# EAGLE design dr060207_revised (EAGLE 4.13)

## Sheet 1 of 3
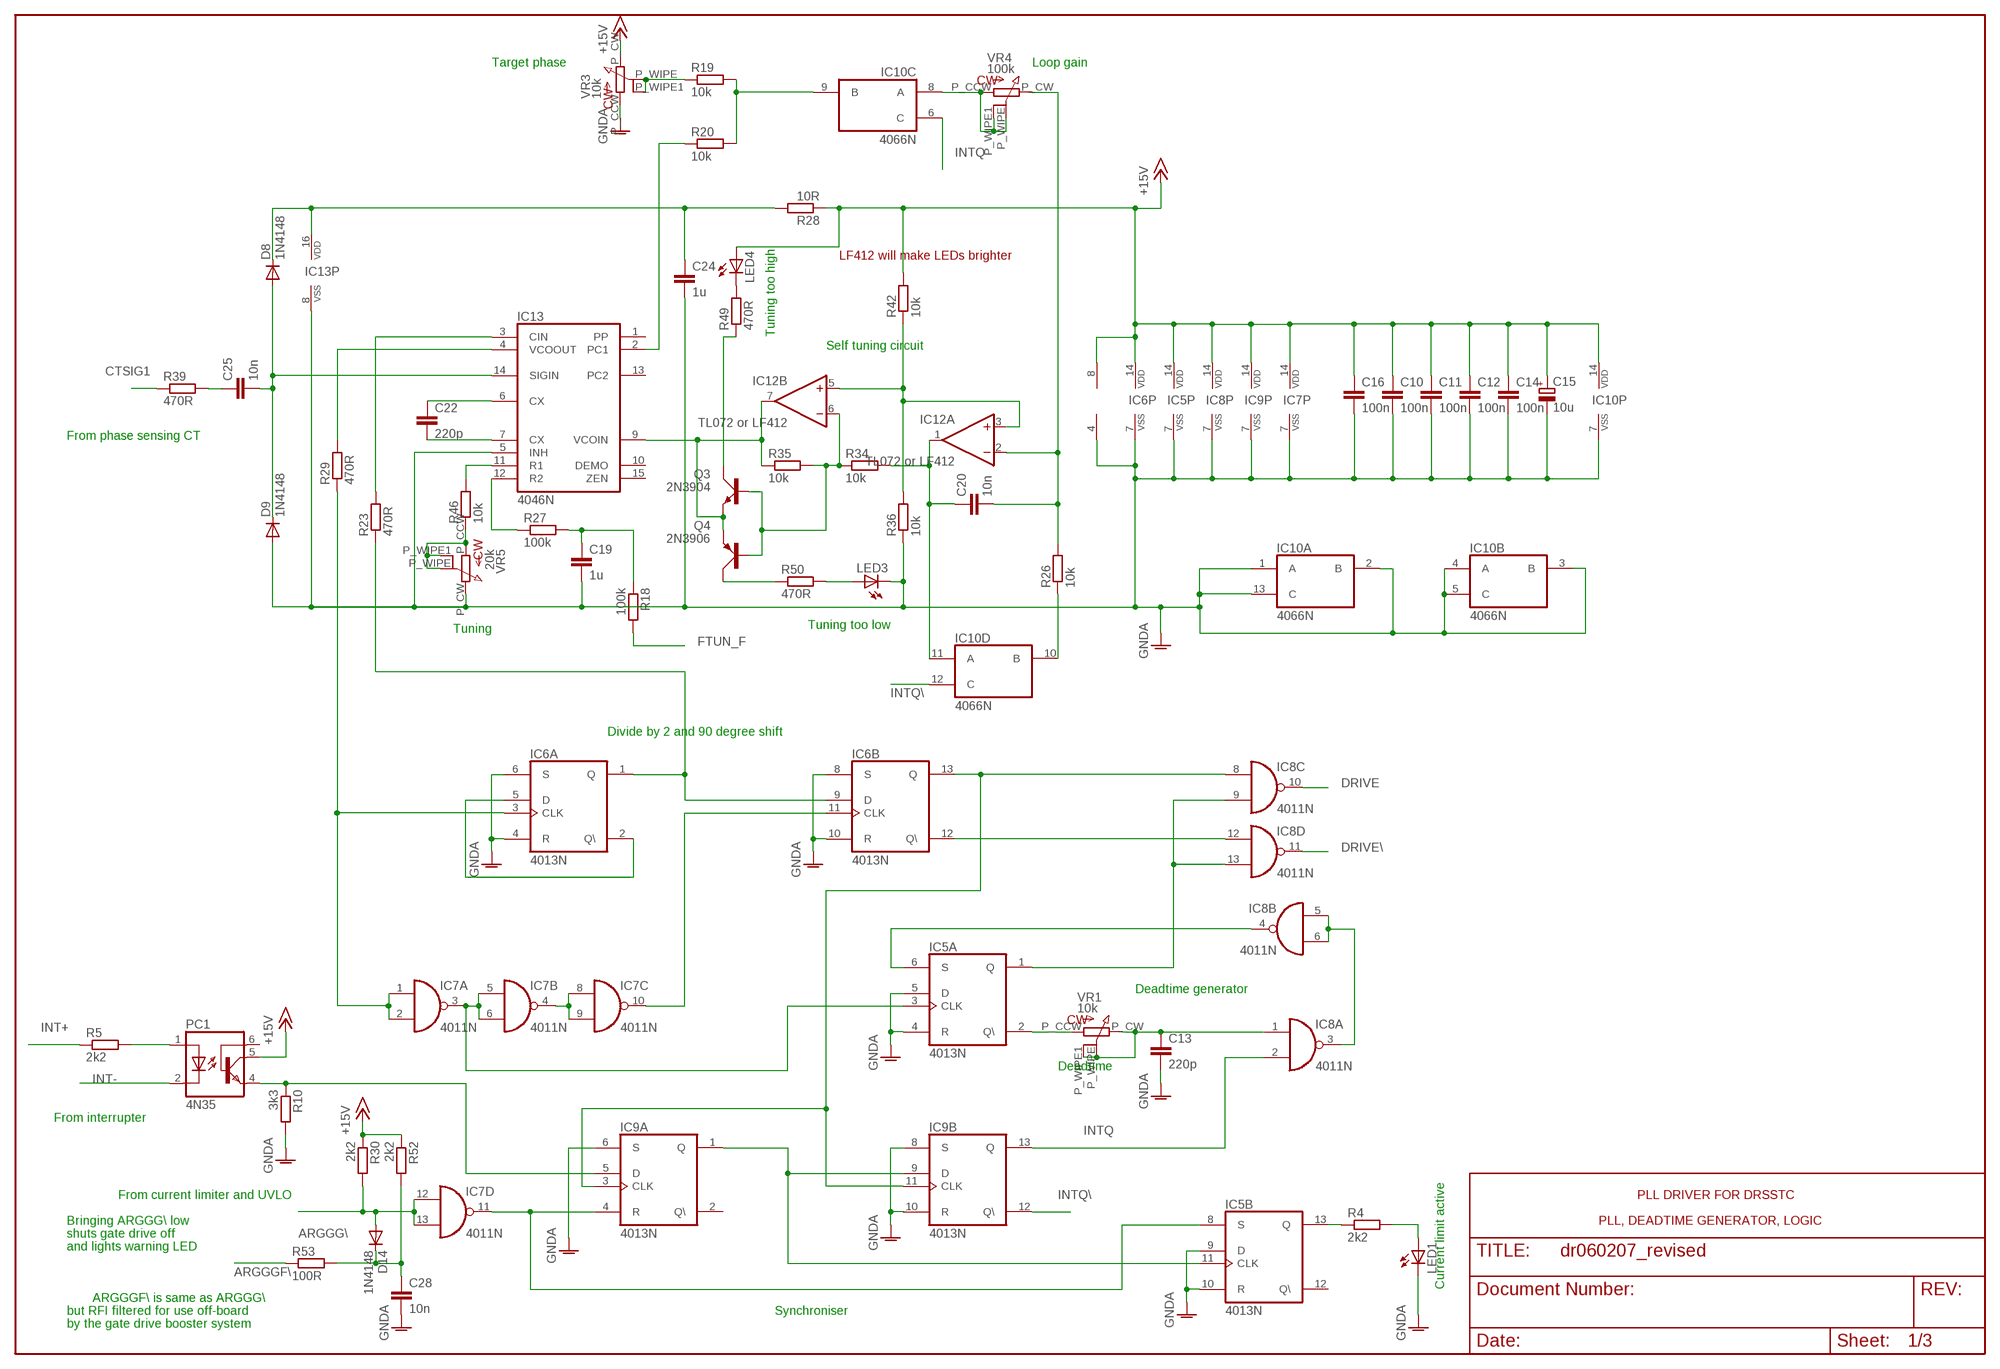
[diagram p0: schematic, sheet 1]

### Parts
C10  100n  C-EU050-025X075  [C050-025X075]
C11  100n  C-EU050-025X075  [C050-025X075]
C12  100n  C-EU050-025X075  [C050-025X075]
C13  220p  C-EU050-025X075  [C050-025X075]
C14  100n  C-EU050-025X075  [C050-025X075]
C15  10u  CPOL-EUTT6D6  [TT5D6]
C16  100n  C-EU050-025X075  [C050-025X075]
C19  1u  C-EU050-025X075  [C050-025X075]
C20  10n  C-EU050-025X075  [C050-025X075]
C22  220p  C-EU050-025X075  [C050-025X075]
C24  1u  C-EU050-055X075  [C050-055X075]
C25  10n  C-EU050-025X075  [C050-025X075]
C28  10n  C-EU050-025X075  [C050-025X075]
D8  1N4148  [DO35-10]
D9  1N4148  [DO35-10]
D14  1N4148  [DO35-10]
IC5  4013N  [DIL14]
IC6  4013N  [DIL14]
IC7  4011N  [DIL14]
IC8  4011N  [DIL14]
IC9  4013N  [DIL14]
IC10  4066N  [DIL14]
IC12  TL072 or LF412  2AMP_P8+4N  [DIL08]
IC13  4046N  [DIL16]
LED1  LED5MM  [LED5MM]
LED3  LED5MM  [LED5MM]
LED4  LED5MM  [LED5MM]
PC1  4N35  [DIL06]
Q3  2N3904  [TO92D]
Q4  2N3906  [TO92D]
R4  2k2  R-EU_0207/10  [0207/10]
R5  2k2  R-EU_0207/10  [0207/10]
R10  3k3  R-EU_0207/10  [0207/10]
R18  100k  R-EU_0207/10  [0207/10]
R19  10k  R-EU_0207/10  [0207/10]
R20  10k  R-EU_0207/10  [0207/10]
R23  470R  R-EU_0207/10  [0207/10]
R26  10k  R-EU_0207/10  [0207/10]
R27  100k  R-EU_0207/10  [0207/10]
R28  10R  R-EU_0207/10  [0207/10]
R29  470R  R-EU_0207/10  [0207/10]
R30  2k2  R-EU_0207/10  [0207/10]
R34  10k  R-EU_0207/10  [0207/10]
R35  10k  R-EU_0207/10  [0207/10]
R36  10k  R-EU_0207/10  [0207/10]
R39  470R  R-EU_0207/10  [0207/10]
R42  10k  R-EU_0207/10  [0207/10]
R46  10k  R-EU_0207/10  [0207/10]
R49  470R  R-EU_0207/10  [0207/10]
R50  470R  R-EU_0207/10  [0207/10]
R52  2k2  R-EU_0207/10  [0207/10]
R53  100R  R-EU_0207/10  [0207/10]
VR1  10k  POT  [SPECTROL149]
VR3  10k  POT  [SPECTROL149]
VR4  100k  POT  [SPECTROL149]
VR5  20k  POT  [SPECTROL149]

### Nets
+15V: C10.1 C11.1 C12.1 C14.1 C15.+ C16.1 IC5.14(P:VDD) IC6.14(P:VDD) IC7.14(P:VDD) IC8.14(P:VDD) IC9.14(P:VDD) IC10.14(P:VDD) IC12.8(P:V+) LED4.A PC1.5(COL) R28.1 R30.1 R42.2 R52.1 VR3.P_CW(CW) ; also sheet 2,3
ARGGG\: D14.A IC7.12(D:I0) IC7.13(D:I1) R30.2 ; also sheet 2
ARGGGF\: R53.1 ; also sheet 3
CTSIG1: R39.1 ; also sheet 3
DRIVE: IC8.10(C:O) ; also sheet 3
DRIVE\: IC8.11(D:O) ; also sheet 3
FTUN_F: R18.2 ; also sheet 3
GNDA: C10.2 C11.2 C12.2 C13.2 C14.2 C15.- C16.2 C19.2 C24.2 C28.2 D9.A IC5.4(A:R) IC5.5(A:D) IC5.7(P:VSS) IC5.9(B:D) IC5.10(B:R) IC6.4(A:R) IC6.6(A:S) IC6.7(P:VSS) IC6.8(B:S) IC6.10(B:R) IC7.7(P:VSS) IC8.7(P:VSS) IC9.6(A:S) IC9.7(P:VSS) IC9.8(B:S) IC9.10(B:R) IC10.1(A:A) IC10.2(A:B) IC10.3(B:B) IC10.4(B:A) IC10.5(B:C) IC10.7(P:VSS) IC10.13(A:C) IC12.4(P:V-) IC13.5(INH) IC13.8(VSS) LED1.K(C) LED3.K(C) R10.2 R36.1 VR3.P_CCW(CCW) VR5.P_CW(CW) ; also sheet 2,3
INT+: R5.1 ; also sheet 3
INT-: PC1.2(C) ; also sheet 3
INTQ: IC8.2(A:I1) IC9.13(B:Q) IC10.6(C:C)
INTQ\: IC9.12(B:Q\) IC10.12(D:C)
N$1: C22.2 IC13.7(CX)
N$2: IC10.10(D:B) R26.1
N$3: IC12.7(B:OUT) IC13.9(VCOIN) Q3.E Q4.E R35.1
N$4: IC12.3(A:+IN) IC12.5(B:+IN) R36.2 R42.1
N$5: C24.1 D8.C IC13.16(VDD) R28.2
N$7: C22.1 IC13.6(CX)
N$8: IC6.2(A:Q\) IC6.5(A:D)
N$9: IC6.1(A:Q) IC6.9(B:D) R23.1
N$10: IC13.3(CIN) R23.2
N$11: IC13.11(R1) R46.2
N$12: IC9.5(A:D) PC1.4(EMI) R10.1
N$13: IC5.3(A:CLK) IC7.3(A:O) IC7.5(B:I0) IC7.6(B:I1)
N$14: R46.1 VR5.P_CCW(CCW) VR5.P_WIPE1(WIPE1) VR5.P_WIPE(WIPE)
N$16: IC7.4(B:O) IC7.8(C:I0) IC7.9(C:I1)
N$17: C20.1 IC10.11(D:A) IC12.1(A:OUT) R34.2
N$18: IC6.11(B:CLK) IC7.10(C:O)
N$19: C20.2 IC12.2(A:-IN) R26.2 VR4.P_CW(CW)
N$20: C25.2 D8.A D9.C IC13.14(SIGIN)
N$22: IC13.4(VCOOUT) R29.2
N$23: IC6.3(A:CLK) IC7.1(A:I0) IC7.2(A:I1) R29.1
N$26: PC1.1(A) R5.2
N$29: C25.1 R39.2
N$31: C13.1 IC8.1(A:I0) VR1.P_CW(CW) VR1.P_WIPE1(WIPE1) VR1.P_WIPE(WIPE)
N$32: IC5.1(A:Q) IC8.9(C:I1) IC8.13(D:I1)
N$33: IC6.13(B:Q) IC8.8(C:I0) IC9.3(A:CLK) IC9.11(B:CLK)
N$34: IC6.12(B:Q\) IC8.12(D:I0)
N$35: IC5.6(A:S) IC8.4(B:O)
N$36: IC8.3(A:O) IC8.5(B:I0) IC8.6(B:I1)
N$39: IC5.11(B:CLK) IC9.1(A:Q) IC9.9(B:D)
N$40: IC5.8(B:S) IC7.11(D:O) IC9.4(A:R)
N$42: IC12.6(B:-IN) Q3.B Q4.B R34.1 R35.2
N$43: LED1.A R4.2
N$44: IC5.13(B:Q) R4.1
N$47: IC10.9(C:B) R19.2 R20.2
N$48: IC13.2(PC1) R20.1
N$49: R19.1 VR3.P_WIPE1(WIPE1) VR3.P_WIPE(WIPE)
N$50: IC10.8(C:A) VR4.P_CCW(CCW) VR4.P_WIPE1(WIPE1) VR4.P_WIPE(WIPE)
N$51: Q4.C R50.1
N$52: LED3.A R50.2
N$53: LED4.K(C) R49.2
N$54: Q3.C R49.1
N$70: IC5.2(A:Q\) VR1.P_CCW(CCW)
N$71: IC13.12(R2) R27.1
N$72: C19.1 R18.1 R27.2
N$666: C28.1 D14.C R52.2 R53.2
Unconnected: IC5.12(B:Q\) IC9.2(A:Q\) IC13.1(PP) IC13.10(DEMO) IC13.13(PC2) IC13.15(ZEN) PC1.6(BAS)

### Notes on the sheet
- Target phase | Loop gain
- LF412 will make LEDs brighter
- Tuning too high
- Self tuning circuit
- From phase sensing CT
- Tuning too low
- Tuning
- Divide by 2 and 90 degree shift
- Deadtime generator
- Deadtime
- From interrupter
- From current limiter and UVLO | PLL DRIVER FOR DRSSTC
- Bringing ARGGG\ low | PLL, DEADTIME GENERATOR, LOGIC
- shuts gate drive off
- and lights warning LED
- Current limit active
- ARGGGF\ is same as ARGGG\
- but RFI filtered for use off-board | Synchroniser
- by the gate drive booster system

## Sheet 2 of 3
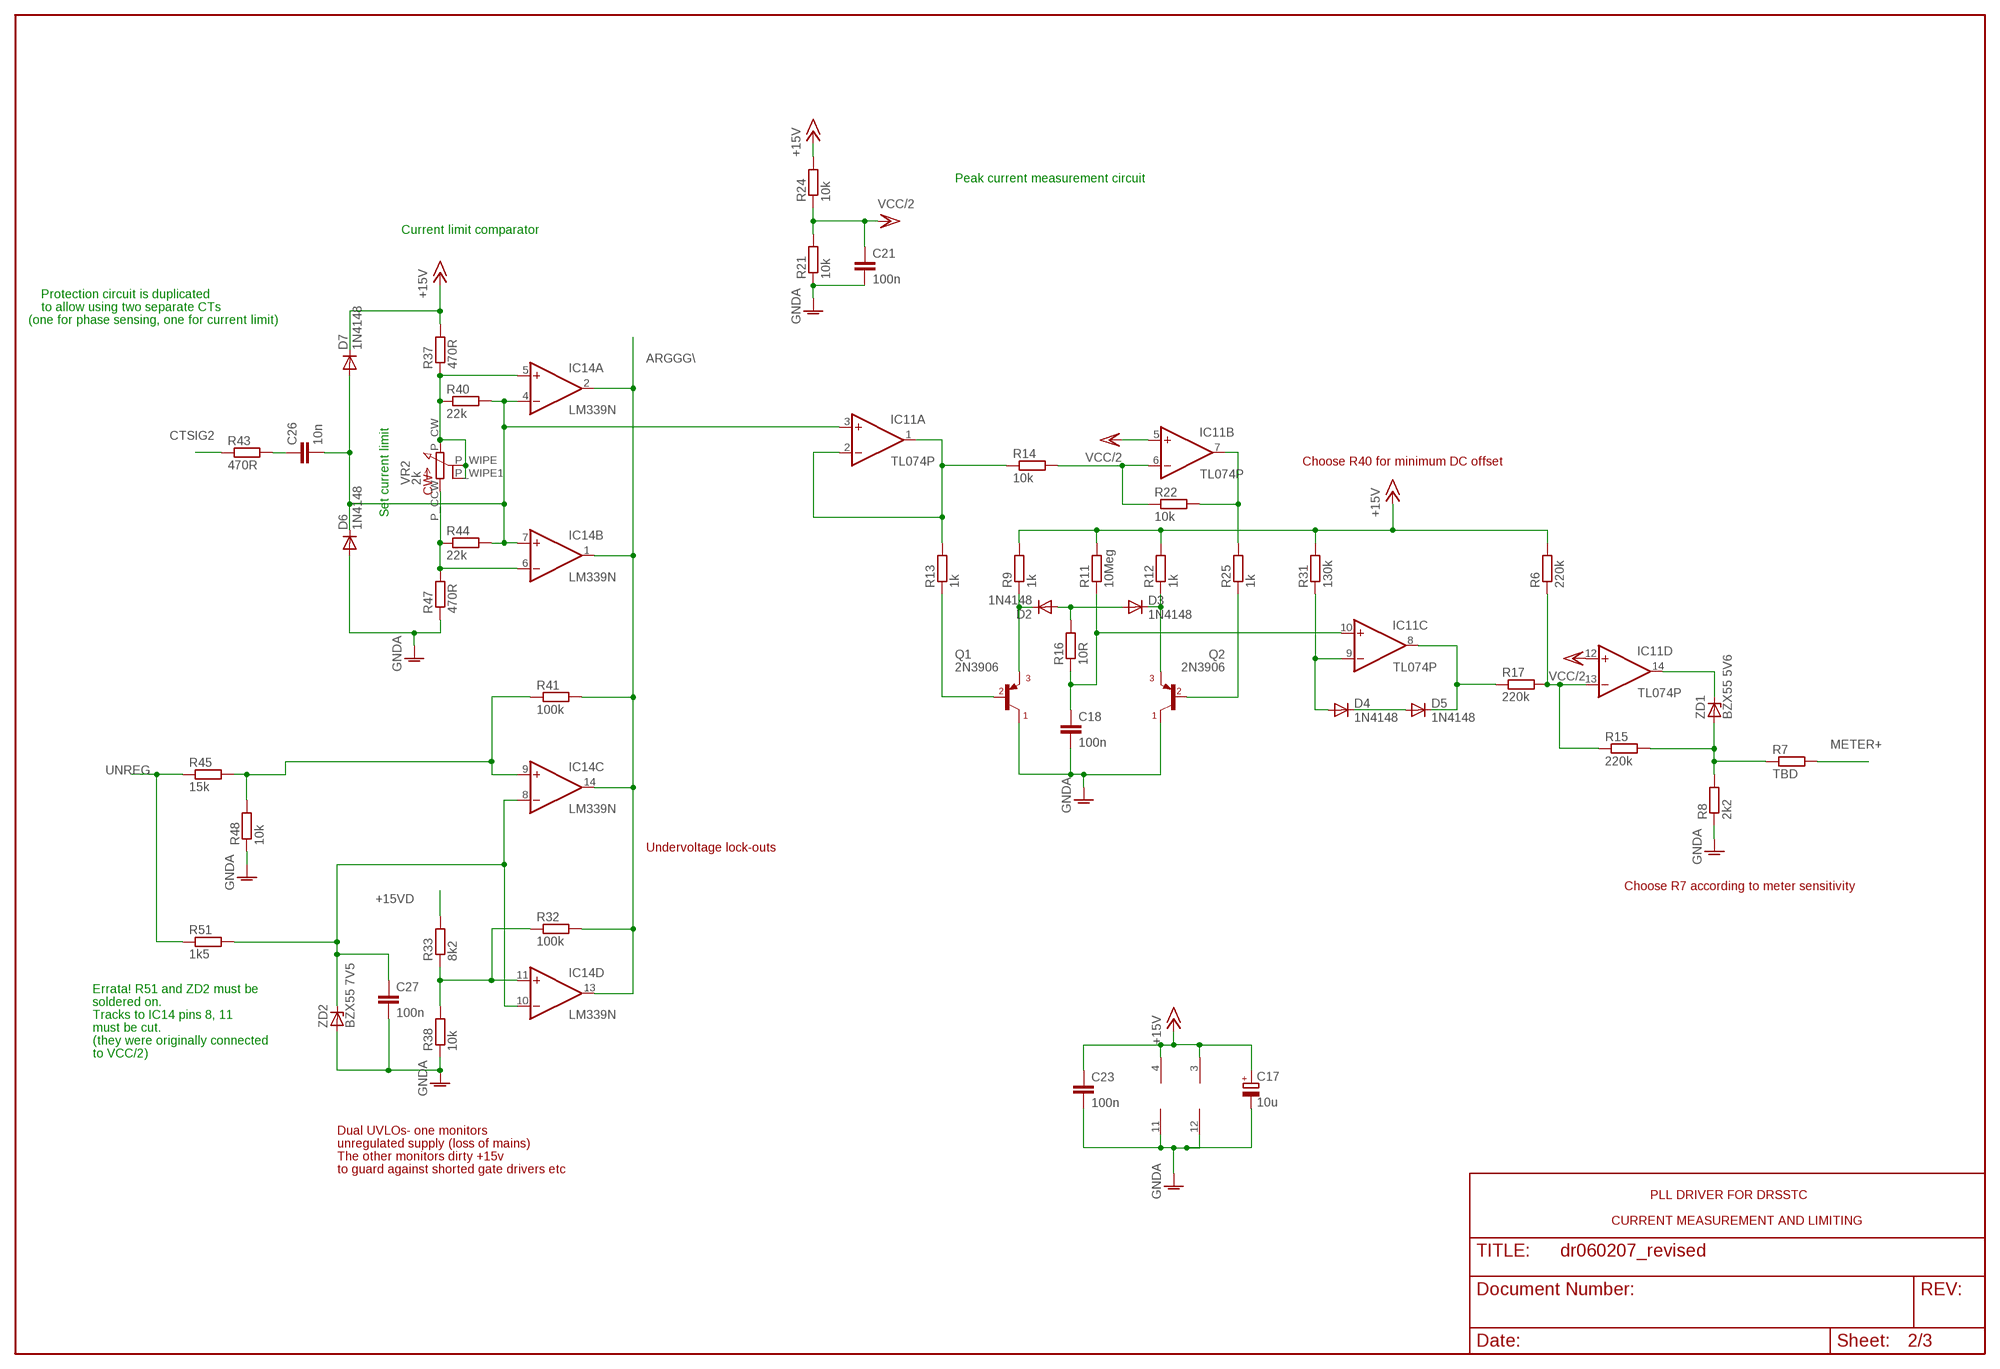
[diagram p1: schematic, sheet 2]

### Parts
C17  10u  CPOL-EUTT6D6  [TT5D6]
C18  100n  C-EU050-025X075  [C050-025X075]
C21  100n  C-EU050-025X075  [C050-025X075]
C23  100n  C-EU050-025X075  [C050-025X075]
C26  10n  C-EU050-025X075  [C050-025X075]
C27  100n  C-EU050-025X075  [C050-025X075]
D2  1N4148  [DO35-10]
D3  1N4148  [DO35-10]
D4  1N4148  [DO35-10]
D5  1N4148  [DO35-10]
D6  1N4148  [DO35-10]
D7  1N4148  [DO35-10]
IC11  TL074P  [DIL14]
IC14  LM339N  [DIL14]
Q1  2N3906  [TO92]
Q2  2N3906  [TO92]
R6  220k  R-EU_0207/10  [0207/10]
R7  TBD  R-EU_0207/10  [0207/10]
R8  2k2  R-EU_0207/10  [0207/10]
R9  1k  R-EU_0207/10  [0207/10]
R11  10Meg  R-EU_0207/10  [0207/10]
R12  1k  R-EU_0207/10  [0207/10]
R13  1k  R-EU_0207/10  [0207/10]
R14  10k  R-EU_0207/10  [0207/10]
R15  220k  R-EU_0207/10  [0207/10]
R16  10R  R-EU_0207/10  [0207/10]
R17  220k  R-EU_0207/10  [0207/10]
R21  10k  R-EU_0207/10  [0207/10]
R22  10k  R-EU_0207/10  [0207/10]
R24  10k  R-EU_0207/10  [0207/10]
R25  1k  R-EU_0207/10  [0207/10]
R31  130k  R-EU_0207/10  [0207/10]
R32  100k  R-EU_0207/10  [0207/10]
R33  8k2  R-EU_0207/10  [0207/10]
R37  470R  R-EU_0207/10  [0207/10]
R38  10k  R-EU_0207/10  [0207/10]
R40  22k  R-EU_0207/10  [0207/10]
R41  100k  R-EU_0207/10  [0207/10]
R43  470R  R-EU_0207/10  [0207/10]
R44  22k  R-EU_0207/10  [0207/10]
R45  15k  R-EU_0207/10  [0207/10]
R47  470R  R-EU_0207/10  [0207/10]
R48  10k  R-EU_0207/10  [0207/10]
R51  1k5  R-EU_0207/10  [0207/10]
VR2  2k  POT  [SPECTROL149]
ZD1  BZX55 5V6  BZX55  [DO35Z10]
ZD2  BZX55 7V5  BZX55  [DO35Z10]

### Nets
+15V: C17.+ C23.1 D7.C IC11.4(P:V+) IC14.3(P:V+) R6.2 R9.2 R11.2 R12.2 R24.2 R31.2 R37.2 ; also sheet 1,3
+15VD: R33.2 ; also sheet 3
ARGGG\: IC14.1(B:OUT) IC14.2(A:OUT) IC14.13(D:OUT) IC14.14(C:OUT) R32.2 R41.2 ; also sheet 1
CTSIG2: R43.1 ; also sheet 3
GNDA: C17.- C18.2 C21.2 C23.2 C27.2 D6.A IC11.11(P:V-) IC14.12(P:GND) Q1.1(C) Q2.1(C) R8.1 R21.1 R38.1 R47.1 R48.1 ZD2.A ; also sheet 1,3
METER+: R7.2 ; also sheet 3
N$24: IC14.9(C:+IN) R41.1 R45.2 R48.2
N$27: IC11.6(B:-IN) R14.2 R22.1
N$28: IC11.1(A:OUT) IC11.2(A:-IN) R13.2 R14.1
N$37: C26.1 R43.2
N$38: IC14.11(D:+IN) R32.1 R33.1 R38.2
N$41: IC11.7(B:OUT) R22.2 R25.2
N$45: C26.2 D6.C D7.A IC11.3(A:+IN) IC14.4(A:-IN) IC14.7(B:+IN) R40.2 R44.2
N$46: Q1.2(B) R13.1
N$55: IC14.6(B:-IN) R44.1 R47.2 VR2.P_CCW(CCW)
N$56: IC14.5(A:+IN) R37.1 R40.1 VR2.P_CW(CW) VR2.P_WIPE1(WIPE1) VR2.P_WIPE(WIPE)
N$57: Q2.2(B) R25.1
N$58: D2.C Q1.3(E) R9.1
N$59: D3.C Q2.3(E) R12.1
N$60: D2.A D3.A R16.2
N$61: C18.1 IC11.10(C:+IN) R11.1 R16.1
N$63: D5.C IC11.8(C:OUT) R17.1
N$64: D4.C D5.A
N$65: D4.A IC11.9(C:-IN) R31.1
N$66: IC11.13(D:-IN) R6.1 R15.1 R17.2
N$67: IC11.14(D:OUT) ZD1.C
N$68: R7.1 R8.2 R15.2 ZD1.A
N$75: C27.1 IC14.8(C:-IN) IC14.10(D:-IN) R51.2 ZD2.C
UNREG: R45.1 R51.1 ; also sheet 3
VCC/2: C21.1 IC11.5(B:+IN) IC11.12(D:+IN) R21.2 R24.1

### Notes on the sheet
- Peak current measurement circuit
- Current limit comparator
- Protection circuit is duplicated
- to allow using two separate CTs
- (one for phase sensing, one for current limit)
- Choose R40 for minimum DC offset
- Set current limit
- Undervoltage lock-outs
- Choose R7 according to meter sensitivity
- Errata! R51 and ZD2 must be
- soldered on.
- Tracks to IC14 pins 8, 11
- must be cut.
- (they were originally connected
- to VCC/2)
- Dual UVLOs- one monitors
- unregulated supply (loss of mains)
- The other monitors dirty +15v
- to guard against shorted gate drivers etc
- PLL DRIVER FOR DRSSTC
- CURRENT MEASUREMENT AND LIMITING

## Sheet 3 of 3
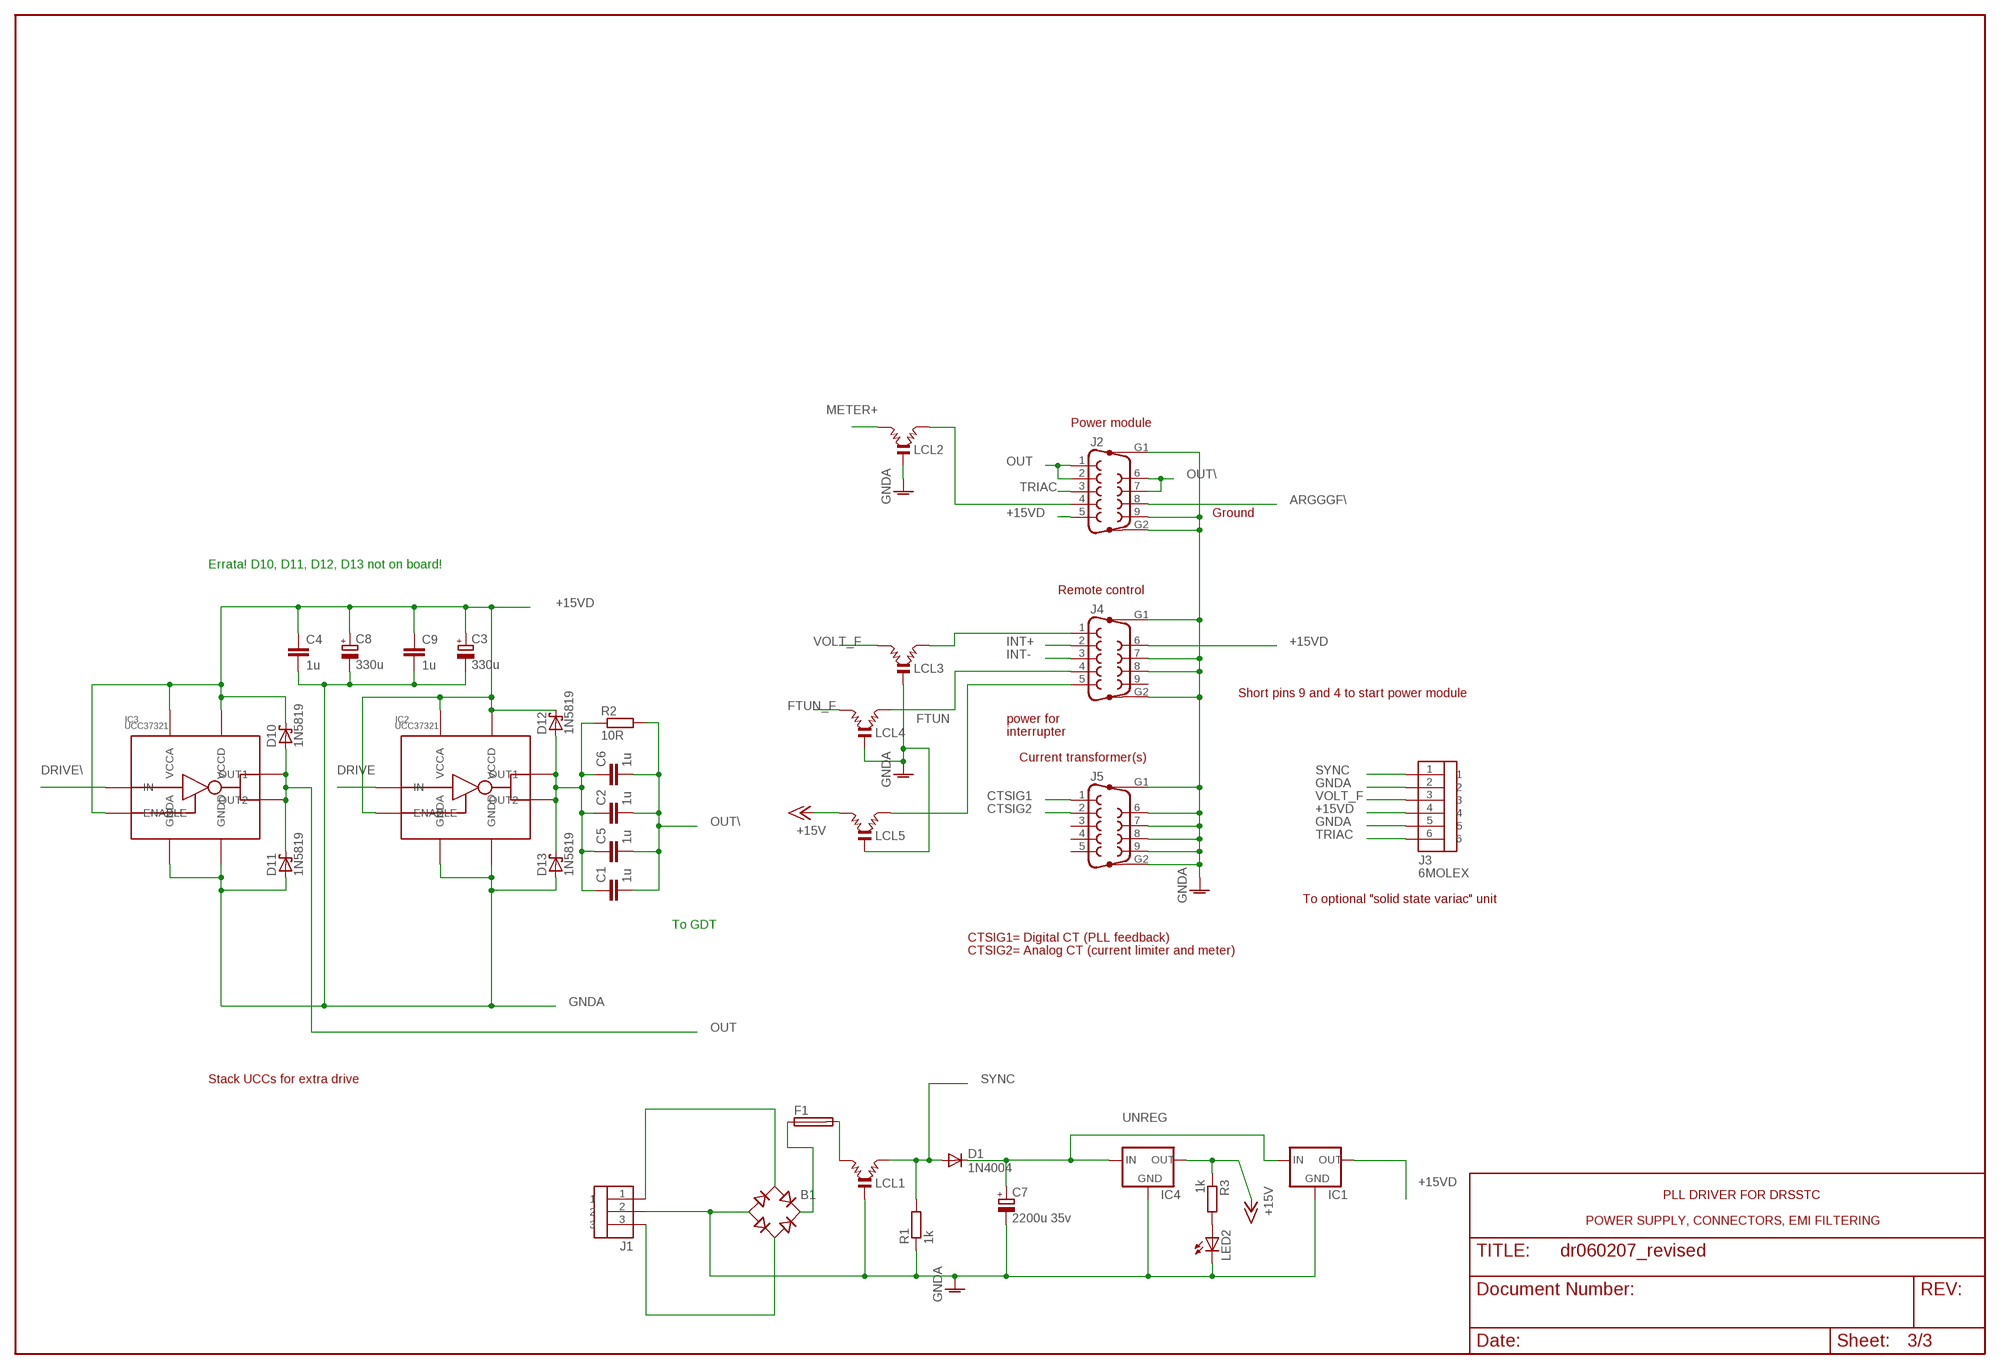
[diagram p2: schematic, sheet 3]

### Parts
B1  RB1A  [RB1A]
C1  1u  C-EU050-055X075  [C050-055X075]
C2  1u  C-EU050-055X075  [C050-055X075]
C3  330u  CPOL-EUE3.5-10  [E3,5-10]
C4  1u  C-EU050-025X075  [C050-025X075]
C5  1u  C-EU050-055X075  [C050-055X075]
C6  1u  C-EU050-055X075  [C050-055X075]
C7  2200u 35v  CPOL-EUE7.5-18  [E7,5-18]
C8  330u  CPOL-EUE3.5-10  [E3,5-10]
C9  1u  C-EU050-025X075  [C050-025X075]
D1  1N4004  [DO41-10]
D10  1N5819  SCHOTTKY-DIODECORNFIELD  [CORNFIELD]
D11  1N5819  SCHOTTKY-DIODECORNFIELD  [CORNFIELD]
D12  1N5819  SCHOTTKY-DIODECORNFIELD  [CORNFIELD]
D13  1N5819  SCHOTTKY-DIODECORNFIELD  [CORNFIELD]
F1  SH22,5  [SH22,5]
IC1  78XXS  [78XXS]
IC2  UCC37321  [DIL08]
IC3  UCC37321  [DIL08]
IC4  78XXS  [78XXS]
J1  P3-5  [P3-5]
J2  F09HP  [F09HP]
J3  6MOLEX  [6MOLEX]
J4  F09HP  [F09HP]
J5  F09HP  [F09HP]
LCL1  LCL  [LCL]
LCL2  LCL  [LCL]
LCL3  LCL  [LCL]
LCL4  LCL  [LCL]
LCL5  LCL  [LCL]
LED2  LED5MM  [LED5MM]
R1  1k  R-EU_0207/10  [0207/10]
R2  10R  R-EU_0207/10  [0207/10]
R3  1k  R-EU_0207/10  [0207/10]

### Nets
+15V: IC4.OUT LCL5.1 R3.1 ; also sheet 1,2
+15VD: C3.+ C4.1 C8.+ C9.1 D10.C D12.C IC1.OUT IC2.1(VCCA) IC2.3(ENABLE) IC2.8(VCCD) IC3.1(VCCA) IC3.3(ENABLE) IC3.8(VCCD) J2.5 J3.4 J4.6 ; also sheet 2
ARGGGF\: J2.8 ; also sheet 1
CTSIG1: J5.1 ; also sheet 1
CTSIG2: J5.2 ; also sheet 2
DRIVE: IC2.2(IN) ; also sheet 1
DRIVE\: IC3.2(IN) ; also sheet 1
FTUN: J4.4 LCL4.2
FTUN_F: LCL4.1 ; also sheet 1
GNDA: B1.- C3.- C4.2 C7.- C8.- C9.2 D11.A D13.A IC1.GND IC2.4(GNDA) IC2.5(GNDD) IC3.4(GNDA) IC3.5(GNDD) IC4.GND J1.2 J2.9 J2.G1 J2.G2 J3.2 J3.5 J4.7 J4.8 J4.G1 J4.G2 J5.6 J5.7 J5.8 J5.9 J5.G1 J5.G2 LCL1.0(GND) LCL2.0(GND) LCL3.0(GND) LCL4.0(GND) LCL5.0(GND) LED2.K(C) R1.1 ; also sheet 1,2
INT+: J4.2 ; also sheet 1
INT-: J4.3 ; also sheet 1
METER+: LCL2.1 ; also sheet 2
N$6: J4.1 LCL3.2
N$15: J2.4 LCL2.2
N$21: B1.+ F1.1
N$25: B1.AC1 J1.1
N$30: J4.5 LCL5.2
N$62: B1.AC2 J1.3
N$69: LED2.A R3.2
N$73: C1.1 C2.1 C5.1 C6.1 D12.A D13.C IC2.6(OUT2) IC2.7(OUT1) R2.1
N$74: F1.2 LCL1.1
OUT: D10.A D11.C IC3.6(OUT2) IC3.7(OUT1) J2.1 J2.2
OUT\: C1.2 C2.2 C5.2 C6.2 J2.6 J2.7 R2.2
SYNC: D1.A J3.1 LCL1.2 R1.2
TRIAC: J2.3 J3.6
UNREG: C7.+ D1.C IC1.IN IC4.IN ; also sheet 2
VOLT_F: J3.3 LCL3.1
Unconnected: J4.9 J5.3 J5.4 J5.5

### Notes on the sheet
- Power module
- Ground
- Errata! D10, D11, D12, D13 not on board!
- Remote control
- Short pins 9 and 4 to start power module
- power for
- interrupter
- Current transformer(s)
- To optional "solid state variac" unit
- To GDT
- CTSIG1= Digital CT (PLL feedback)
- CTSIG2= Analog CT (current limiter and meter)
- Stack UCCs for extra drive
- PLL DRIVER FOR DRSSTC
- POWER SUPPLY, CONNECTORS, EMI FILTERING

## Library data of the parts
B1 = rectifier:RB1A: RECTIFIER 1 A
C1 C2 C4-C6 C9-C14 C16 C18 C19 C21-C27 = rcl:C-EU: CAPACITOR, European symbol
C3 C7 C8 C15 C17 = rcl:CPOL-EU: POLARIZED CAPACITOR, European symbol
C20 C28 = rcl_dm:C-EU: CAPACITOR, European symbol
D1 = diode:1N4004: DIODE
D2-D9 D14 = diode:1N4148: DIODE
D10-D13 = diode:SCHOTTKY-DIODE: Schottky Diode
F1 = fuse:SH22,5: FUSE HOLDER
IC1 IC4 = v-reg:78XXS: VOLTAGE REGULATOR
IC2 IC3 = tesla:UCC37321
IC5 IC6 IC9 = 40xx:4013: Dual D FLIP FLOP, set/reset
IC7 IC8 = 40xx:4011: Quad 2-input NAND
IC10 = 40xx:4066: Quad bilateral ANALOG SWITCH
IC11 = linear_optosci:TL074: OP AMP
IC12 = linear:2AMP_P8+4: OP AMP
IC13 = 40xx:4046: Micropower PLL
IC14 = linear_optosci:LM339: Low Power Low Offset Voltage Quad Comparators with open collector; LM139/LM239/LM339/LM2901/LM3302
J1 = CONNDM:P3-5
J2 J4 J5 = con-subd:F09HP: SUB-D
J3 = CONNDM:6MOLEX
LCL1-LCL5 = murata-filter:LCL: FILTER
LED1-LED4 = led:LED: LED
PC1 = optocoupler:4N35: MOTOROLA OPTO COUPLER
Q1 Q2 = transistors_optosci:2N3906: PNP Transistor
Q3 = transistor-small-signal:2N3904: NPN TRANSISTOR
Q4 = transistor-small-signal:2N3906: PNP TRANSISTOR
R1-R53 = rcl:R-EU_: RESISTOR, European symbol
VR1-VR5 = tesla:POT
ZD1 ZD2 = diode:BZX55: Z DIODE

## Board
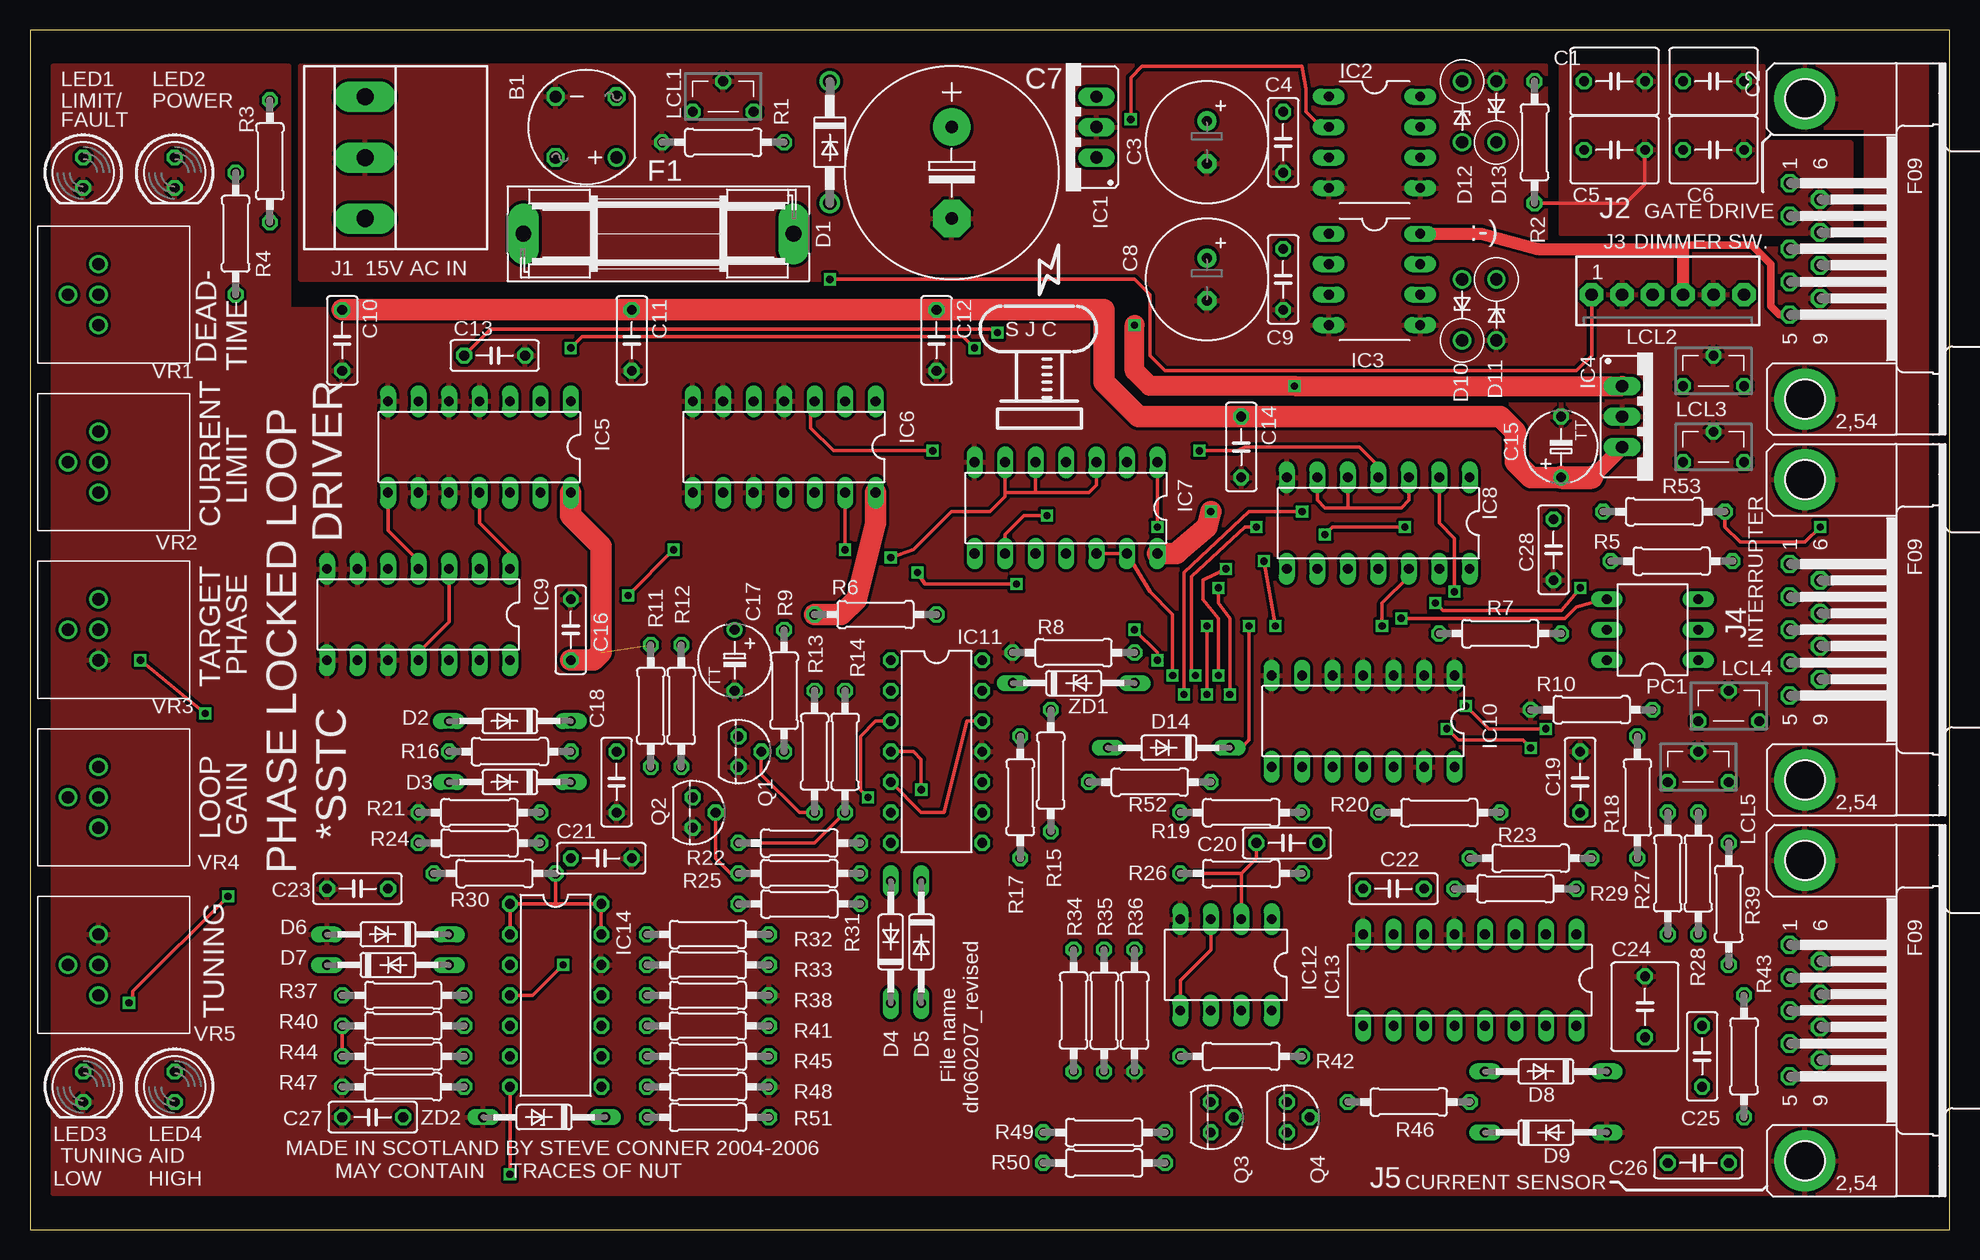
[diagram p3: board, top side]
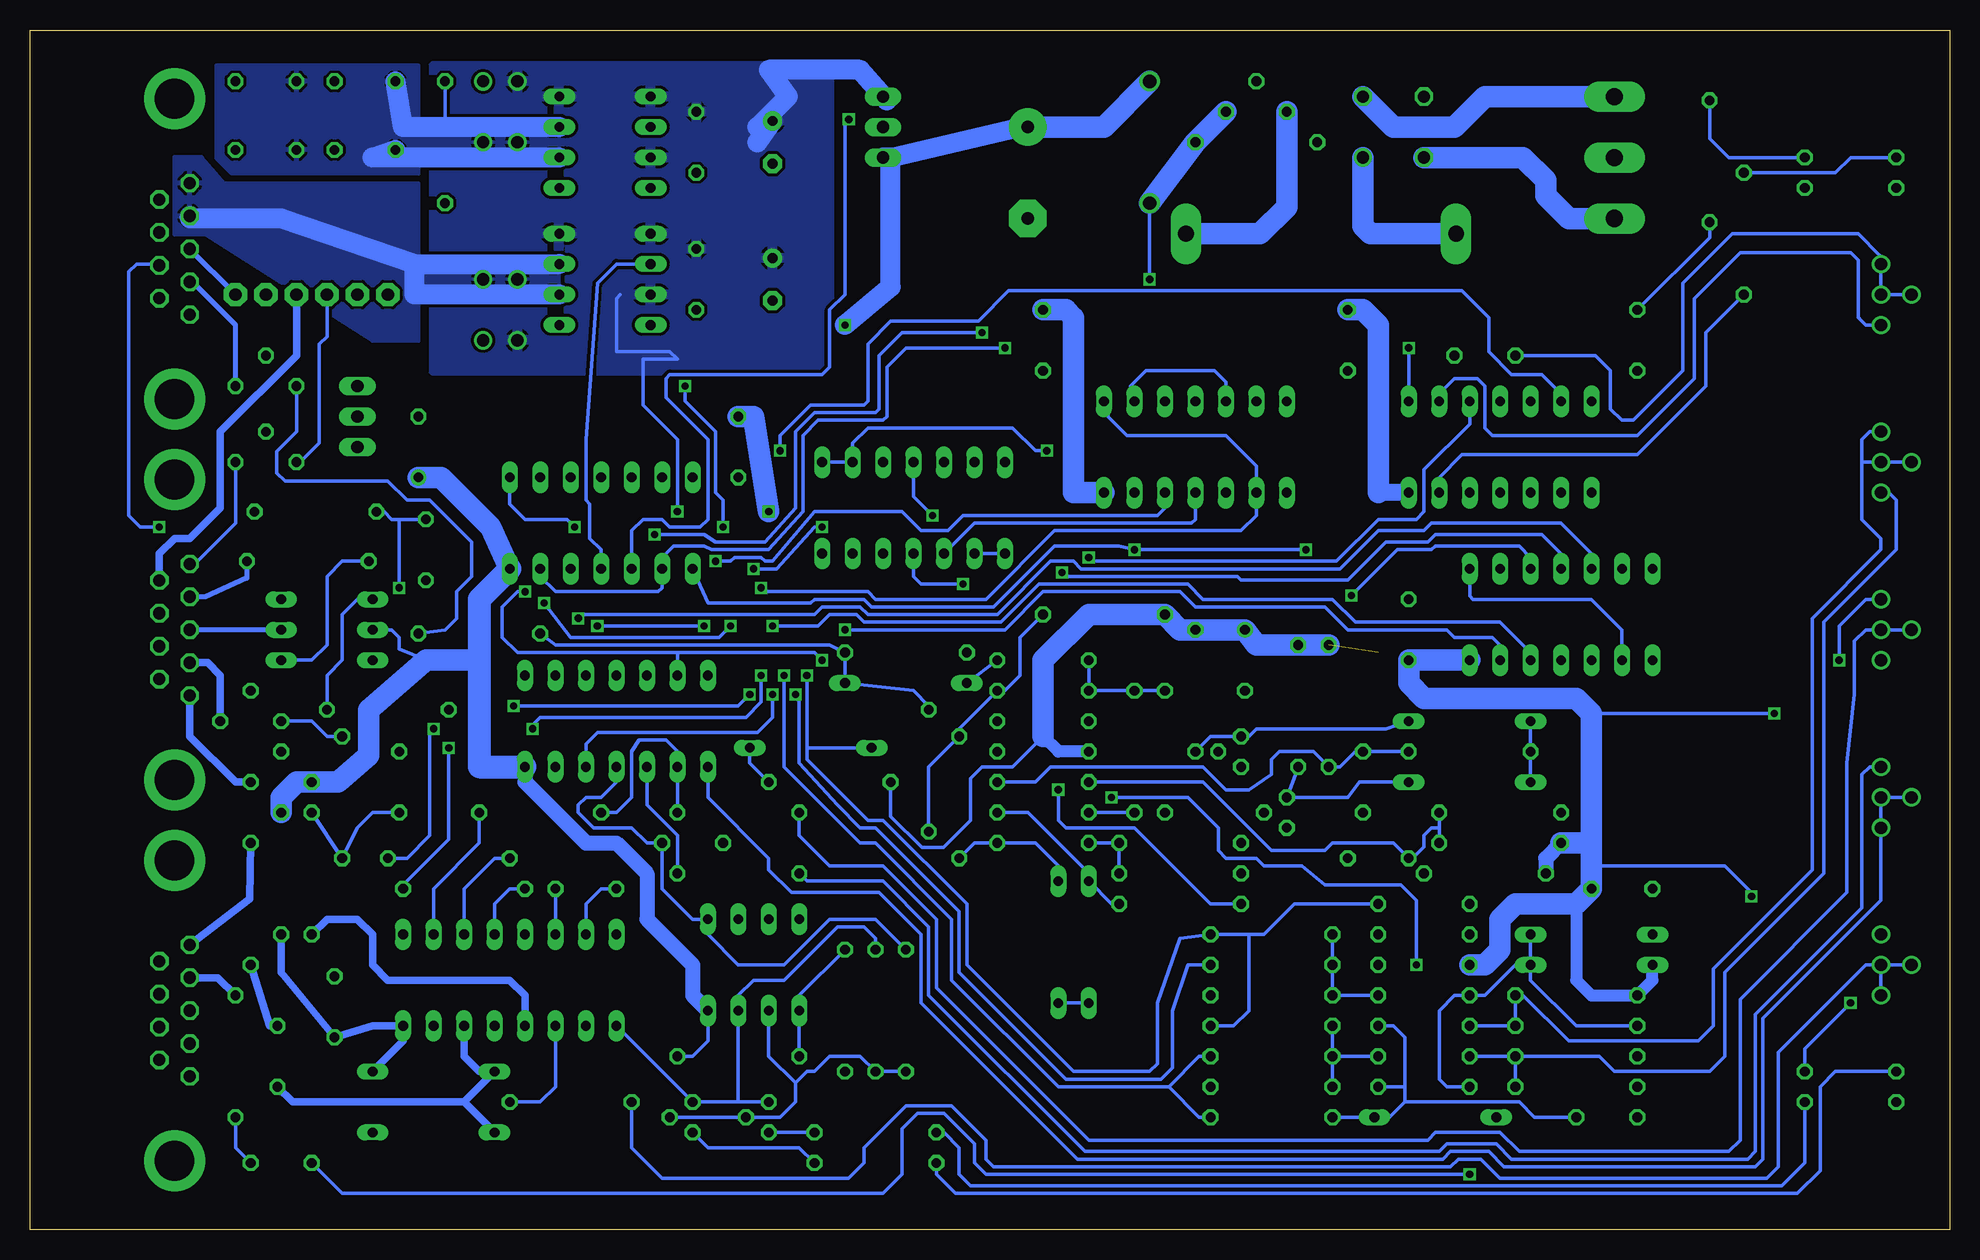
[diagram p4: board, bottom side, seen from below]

Size 160 x 100 mm. Coordinates in mm from the lower left corner, seen from the top.
Outline: 0,0 160,0 160,100 0,100 0,0
Copper layers (1*16): Top 0.035mm / dielectric 1.5mm / Bottom 0.035mm
Design rules "10mil": minimum track width 10mil, minimum drill 23mil, track to track 10mil, track to pad 10mil, pad to pad 10mil, via to via 10mil, smd to smd 0mil, copper to edge 40mil, drill to drill 8mil, minimum pad ring 10mil, minimum via ring 8mil, stop-mask expansion 4mil, vias tented up to drill 0mil, thermal gap 10mil

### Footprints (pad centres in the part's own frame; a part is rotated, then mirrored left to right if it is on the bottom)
RB1A = drill 1.016 round: + -2.54,2.54 | drill 1.016 octagon: - 2.54,-2.54; AC1 2.54,2.54; AC2 -2.54,-2.54
C050-055X075 = drill 0.813 octagon: 1 -2.54,0; 2 2.54,0
E3,5-10 = drill 0.813 pad 1.6 round: + -1.778,0 | drill 0.813 pad 1.6 octagon: - 1.778,0
C050-025X075 = drill 0.813 octagon: 1 -2.54,0; 2 2.54,0
E7,5-18 = drill 1.016 pad 3.15 round: + -3.81,0 | drill 1.016 pad 3.15 octagon: - 3.81,0
TT5D6 = drill 0.813 round: + -2.54,0 | drill 0.813 octagon: - 2.54,0
DO41-10 = drill 1.118 round: A 5.08,0; C -5.08,0
DO35-10 = drill 0.813 long: A 5.08,0; C -5.08,0
CORNFIELD = drill 1.016 round: A -1.27,0; C -6.35,0
SH22,5 = drill 1.321 pad 2.54 long: 1 -11.252,0; 2 11.252,0
78XXS = drill 1.016 long: GND 0,-2.54; IN -2.54,-2.54; OUT 2.54,-2.54
DIL08 = drill 0.813 long: 1 -3.81,-3.81; 2 -1.27,-3.81; 3 1.27,-3.81; 4 3.81,-3.81; 5 3.81,3.81; 6 1.27,3.81; 7 -1.27,3.81; 8 -3.81,3.81
DIL14 = drill 0.813 long: 1 -7.62,-3.81; 2 -5.08,-3.81; 3 -2.54,-3.81; 4 0,-3.81; 5 2.54,-3.81; 6 5.08,-3.81; 7 7.62,-3.81; 8 7.62,3.81; 9 5.08,3.81; 10 2.54,3.81; 11 0,3.81; 12 -2.54,3.81; 13 -5.08,3.81; 14 -7.62,3.81
DIL14' = drill 0.813 octagon: 1 -7.62,-3.81; 2 -5.08,-3.81; 3 -2.54,-3.81; 4 0,-3.81; 5 2.54,-3.81; 6 5.08,-3.81; 7 7.62,-3.81; 8 7.62,3.81; 9 5.08,3.81; 10 2.54,3.81; 11 0,3.81; 12 -2.54,3.81; 13 -5.08,3.81; 14 -7.62,3.81
DIL16 = drill 0.813 long: 1 -8.89,-3.81; 2 -6.35,-3.81; 3 -3.81,-3.81; 4 -1.27,-3.81; 5 1.27,-3.81; 6 3.81,-3.81; 7 6.35,-3.81; 8 8.89,-3.81; 9 8.89,3.81; 10 6.35,3.81; 11 3.81,3.81; 12 1.27,3.81; 13 -1.27,3.81; 14 -3.81,3.81; 15 -6.35,3.81; 16 -8.89,3.81
P3-5 = drill 1.422 pad 2.54 long: 1 0,5.08; 2 0,0; 3 0,-5.08
F09HP = drill 1.016 octagon: 1 -5.486,-1.27; 2 -2.743,-1.27; 3 0,-1.27; 4 2.743,-1.27; 5 5.486,-1.27; 6 -4.115,1.27; 7 -1.372,1.27; 8 1.372,1.27; 9 4.115,1.27 | drill 3.302 pad 5.08 round: G1 -12.522,0; G2 12.522,0
6MOLEX = drill 1.016 pad 1.93 octagon: 1 -6.35,0; 2 -3.81,0; 3 -1.27,0; 4 1.27,0; 5 3.81,0; 6 6.35,0
LCL = drill 0.813 octagon: 0 0,1.27; 1 -2.54,-1.27; 2 2.54,-1.27
LED5MM = drill 0.813 octagon: A -1.27,0; K 1.27,0
DIL06 = drill 0.813 long: 1 -2.54,-3.81; 2 0,-3.81; 3 2.54,-3.81; 4 2.54,3.81; 5 0,3.81; 6 -2.54,3.81
TO92 = drill 0.813 octagon: 1 1.27,0; 2 0,1.905; 3 -1.27,0
TO92D = drill 0.813 octagon: B 0,1.905; C 1.27,0; E -1.27,0
0207/10 = drill 0.813 octagon: 1 -5.08,0; 2 5.08,0
SPECTROL149 = drill 1.016 round: P_CCW 2.54,5.08; P_CW -2.54,5.08; P_WIPE 0,5.08; P_WIPE1 0,2.54
DO35Z10 = drill 0.813 long: A 5.08,0; C -5.08,0

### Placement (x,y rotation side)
B1  46.35,91.91 180 top
C1  132.07,95.72 0 top
C2  140.33,95.72 0 top
C3  98.1,90.64 270 top
C4  104.45,90.64 270 top
C5  132.07,90 0 top
C6  140.33,90 0 top
C7  76.83,88.1 270 top
C8  98.1,79.21 270 top
C9  104.45,79.21 270 top
C10  26.03,74.13 270 top
C11  50.16,74.13 270 top
C12  75.56,74.13 270 top
C13  38.73,72.86 0 top
C14  100.96,65.24 270 top
C15  127.63,65.24 90 top
C16  45.08,50 90 top
C17  58.73,47.46 270 top
C18  48.89,37.3 270 top
C19  129.22,37.3 90 top
C20  104.77,32.22 180 top
C21  47.62,30.95 0 top
C22  113.66,28.41 180 top
C23  27.3,28.41 180 top
C24  134.62,18.57 90 top
C25  139.38,14.44 270 top
C26  139.06,5.55 180 top
C27  28.57,9.36 180 top
C28  126.99,56.67 270 top
D1  66.67,90.64 270 top
D2  40,42.38 180 top
D3  40,37.3 180 top
D4  71.75,23.96 90 top
D5  74.29,23.96 270 top
D6  29.84,24.6 180 top
D7  29.84,22.06 0 top
D8  126.36,13.17 180 top
D9  126.36,8.09 0 top
D10  119.38,80.48 90 top
D11  122.23,72.86 270 top
D12  119.38,89.37 270 top
D13  122.23,96.99 90 top
D14  94.93,40.16 180 top
F1  52.38,83.02 0 top
IC1  86.35,91.91 90 top
IC2  112.07,90.64 270 top
IC3  112.07,79.21 270 top
IC4  135.25,67.78 270 top
IC5  37.46,65.24 180 top
IC6  62.86,65.24 180 top
IC7  86.35,60.16 180 top
IC8  112.39,58.89 180 top
IC9  32.38,51.27 180 top
IC10  111.12,42.38 180 top
IC11  TL074P  [DIL14']  75.56,39.84 270 top
IC12  99.69,22.06 180 top
IC13  120.01,20.79 180 top
IC14  LM339N  [DIL14']  43.81,19.52 270 top
J1  27.93,89.37 180 top
J2  147.95,81.75 270 top
J3  136.52,77.94 0 top
J4  147.95,50 270 top
J5  147.95,18.25 270 top
LCL1  57.78,94.45 0 top
LCL2  140.33,71.59 0 top
LCL3  140.33,65.24 0 top
LCL4  141.6,43.65 0 top
LCL5  139.06,38.57 0 top
LED1  4.44,88.1 270 top
LED2  12.06,88.1 270 top
LED3  4.44,11.9 270 top
LED4  12.06,11.9 270 top
PC1  135.25,50 90 top
Q1  59.05,39.84 270 top
Q2  55.24,34.76 270 top
Q3  98.42,9.36 270 top
Q4  104.77,9.36 270 top
R1  57.78,90.64 0 top
R2  125.41,90.64 270 top
R3  20,89.05 90 top
R4  17.14,83.02 90 top
R5  136.84,55.71 180 top
R6  70.48,51.27 180 top
R7  122.55,49.68 0 top
R8  86.99,48.09 0 top
R9  62.86,44.92 90 top
R10  130.17,43.33 180 top
R11  51.75,43.65 90 top
R12  54.29,43.65 90 top
R13  65.4,39.84 90 top
R14  67.94,39.84 270 top
R15  85.08,38.25 90 top
R16  40,39.84 180 top
R17  82.55,36.03 90 top
R18  133.98,36.03 90 top
R19  100.96,34.76 0 top
R20  117.47,34.76 180 top
R21  37.46,34.76 0 top
R22  64.13,32.22 0 top
R23  125.09,30.95 180 top
R24  37.46,32.22 180 top
R25  64.13,29.68 0 top
R26  100.96,29.68 180 top
R27  136.52,29.68 90 top
R28  139.06,29.68 270 top
R29  123.82,28.41 180 top
R30  38.73,29.68 0 top
R31  64.13,27.14 180 top
R32  56.51,24.6 0 top
R33  56.51,22.06 0 top
R34  86.99,18.25 90 top
R35  89.53,18.25 270 top
R36  92.07,18.25 90 top
R37  31.11,19.52 180 top
R38  56.51,19.52 180 top
R39  141.6,27.14 270 top
R40  31.11,16.98 180 top
R41  56.51,16.98 0 top
R42  100.96,14.44 0 top
R43  142.87,14.44 270 top
R44  31.11,14.44 180 top
R45  56.51,14.44 180 top
R46  114.93,10.63 0 top
R47  31.11,11.9 0 top
R48  56.51,11.9 180 top
R49  89.53,8.09 180 top
R50  89.53,5.55 180 top
R51  56.51,9.36 180 top
R52  93.34,37.3 0 top
R53  136.2,59.84 180 top
VR1  0.63,77.94 270 top
VR2  0.63,63.97 270 top
VR3  0.63,50 270 top
VR4  0.63,36.03 270 top
VR5  0.63,22.06 270 top
ZD1  86.99,45.55 0 top
ZD2  42.86,9.36 180 top

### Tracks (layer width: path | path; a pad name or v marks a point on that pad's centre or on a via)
+15V  (via drill 0.6)  (1 unrouted)
  Top 0.305: IC11.4 73.66,39.84 74.29,39.2 v74.29,36.66 | v14.6,43.02 v9.2,47.46 | v16.5,27.77 8.57,19.84 8.57,19.2 v8.25,18.88
  Top 1.27: 130.17,62.7 IC4.OUT
  Top 1.778: C15.+ 125.09,62.7 123.82,63.97 123.82,66.51 122.55,67.78 C14.1 92.39,67.78 89.53,70.64 89.53,76.67 C12.1 C10.1 | v98.42,59.84 98.1,58.57 95.88,56.67 95.56,56.35 IC7.14 | R6.2 67.62,51.27 68.89,52.54 70.48,58.89 IC6.14 | C16.1 46.98,47.46 47.62,48.09 47.62,56.98 45.08,59.52 IC5.14
  Top 1.93: C15.+ 130.17,62.7
  Bottom 0.305: IC12.8 103.5,15.71 104.77,14.44 R42.2 | v74.29,36.66 74.29,34.12 73.66,33.49 67.94,33.49 61.59,27.14 R31.2 | C10.1 20,82.7 R3.1 | v9.2,47.46 9.2,50.32 6.98,52.54 VR3.P_CW | 29.84,43.02 v14.6,43.02 | LED4.A 12.06,15.08 v8.25,18.88 | 30.16,30.31 29.84,30.31 18.73,30.31 16.5,28.09 v16.5,27.77 | PC1.5 129.85,50 129.22,49.37 129.22,48.41 126.99,47.46 | R52.1 88.26,34.44 85.66,31.85 83.87,31.85 81.59,34.12 81.59,37.62 80.64,38.57 78.1,38.57 75.56,41.11
  Bottom 1.016: 31.11,27.14 31.11,20.79 29.84,19.52 R37.2 24.76,20.79 D7.C | IC11.4 74.29,39.84 75.56,41.11
  Bottom 1.27: IC10.14 118.74,37.3 113.66,32.22 111.12,32.22 108.58,29.68 108.58,25.87 104.77,22.06 104.77,19.52 IC12.8 | R30.1 33.65,30.95 R24.2
  Bottom 1.422: IC5.14 47.62,61.43
  Bottom 1.778: C14.1 99.69,67.78 v98.42,59.84 | C15.+ 125.72,62.7 121.6,58.57 IC8.14 | IC6.14 73.02,61.43 73.02,76.03 73.66,76.67 C12.1 | C11.1 48.89,76.67 47.62,75.4 47.62,61.43 | IC9.14 C16.1 45.08,45.55 43.81,44.28 31.11,44.28 29.84,43.02 29.84,32.22 | IC14.3 38.73,22.06 37.46,23.33 37.46,25.87 36.19,27.14 31.11,27.14 C23.1 29.84,30.31 29.84,32.22 | 29.84,32.22 R24.2 | R11.2 R12.2 57.78,48.73 C17.+ R9.2 64.13,50 R6.2 71.75,51.27 75.56,47.46 75.56,41.11 | R28.1 139.06,36.03 137.79,37.3 LCL5.1 134.3,37.3 131.76,39.52 131.76,43.33 126.99,47.46 122.55,47.46
  Bottom 1.93: IC10.14 122.55,38.57 122.55,47.46 122.55,52.54 IC8.14
+15VD  (via drill 0.6)
  Top 0.305: v96.2,44.6 96.2,54.76 101.59,59.84 v106.04,59.84
  Top 0.61: J2.5 145.82,76.26 145.09,76.99 145.09,80.48 143.5,82.07 138.11,82.07 137.79,81.75
  Top 1.016: J3.4 137.79,81.75 125.72,81.75 120.96,83.02 IC3.8
  Bottom 0.305: R33.2 63.5,22.06 64.77,18.25 64.77,13.49 65.72,12.54 73.66,12.54 82.55,21.42 82.55,26.5 89.53,33.49 90.8,33.49 92.7,35.39 95.88,38.89 95.88,43.97 v96.2,44.6 | v106.04,59.84 106.04,65.88 108.9,68.73 108.9,72.54 106.04,72.54 106.67,73.18 111.12,73.18 111.12,77.62 110.8,77.94
  Bottom 0.61: J3.4 137.79,72.86 144.14,66.51 144.14,60.16 146.68,57.62 147.95,57.62 149.22,56.35 J4.6 149.22,53.81
  Bottom 1.676: IC1.OUT 88.58,94.13 90.8,96.67 98.42,96.67 96.83,94.45 99.37,91.91 | 99.37,90.64 C3.+
  pour Bottom: 93.34,71.59 93.34,96.99 126.36,96.99 126.36,71.59
ARGGG\  (via drill 0.6)
  Top 0.305: v95.24,46.19 95.24,51.27 93.34,53.17 IC7.13 IC7.12 | IC14.2 IC14.1 43.81,27.14 | IC14.13 IC14.14 43.81,27.14 | 43.81,27.14 R30.2
  Bottom 0.305: 58.41,24.6 57.15,24.6 54.61,27.14 IC14.14 | 58.41,24.6 R32.2 64.13,24.28 66.03,18.88 66.03,13.81 66.67,13.17 73.02,13.17 81.91,22.06 81.91,27.14 88.89,34.12 90.16,34.12 95.24,39.2 95.24,40.16 | 95.24,40.16 v95.24,46.19 | R41.2 59.69,16.98 58.41,18.25 58.41,24.6 | 95.24,40.16 D14.A
ARGGGF\  (via drill 0.6)
  Top 0.305: R53.1 141.28,58.57 142.55,57.3 147.95,57.3 v149.22,58.57
  Bottom 0.305: v149.22,58.57 150.81,58.57 151.76,59.52 151.76,79.84 151.12,80.48 149.22,80.48 J2.8
CTSIG1
  Bottom 0.61: J5.1 141.69,27.55 R39.1
CTSIG2
  Bottom 0.61: J5.2 144.34,20.99 R43.1
DRIVE  (via drill 0.6)
  Top 0.305: IC2.2 107.63,91.91 106.36,93.18 106.36,95.08 106.04,96.99 92.7,96.99 91.75,96.04 v91.75,92.55
  Bottom 0.305: IC8.10 109.85,58.25 108.9,59.21 107.31,59.21 106.67,58.57 104.13,58.57 103.5,59.21 103.5,65.88 106.99,69.37 106.99,70.95 106.67,71.27 93.97,71.27 93.34,71.91 93.34,76.67 92.07,77.94 92.07,92.55 v91.75,92.55
DRIVE\
  Bottom 0.305: IC8.11 112.39,56.67 113.34,57.62 113.34,60.48 113.66,60.8 113.66,65.88 112.71,78.89 111.12,80.48 IC3.2
FTUN
  Bottom 0.61: LCL4.2 144.14,46.19 145.21,47.26 J4.4 | J4.4 | J4.4
FTUN_F
  Bottom 0.305: LCL4.1 136.52,42.38 135.25,41.11 R18.2
GNDA
  pour Top: 1.9,96.99 1.9,3.01 158.11,3.01 158.11,96.99 147.95,96.99 147.95,91.91 153.03,91.91 153.03,81.75 126.36,81.75 126.36,96.99 22.54,96.99 22.54,79.21 93.34,79.21 93.34,71.59 131.44,71.59 131.44,68.73 89.53,68.73 89.53,76.67 21.58,76.67 21.58,96.99
INT+
  Bottom 0.406: J4.2 | R5.1 141.92,54.31 145.39,52.74 J4.2 | J4.2 146.75,52.8
INT-
  Bottom 0.406: PC1.2 J4.3
INTQ  (via drill 0.6)
  Top 0.305: v93.97,47.46 93.97,48.09 v92.07,50 | IC8.2 117.47,58.89 118.74,57.62 v118.74,53.17
  Bottom 0.305: 106.04,48.09 IC10.6 | 106.04,48.09 94.61,48.09 v93.97,47.46 | v92.07,50 78.73,50 75.56,53.17 64.13,53.17 62.86,51.91 52.07,51.91 50.16,50 41.91,50 41.27,49.37 38.1,49.37 37.46,48.73 IC9.13 | v118.74,53.17 119.38,53.17 120.64,51.91 120.64,49.37 119.38,48.09 106.04,48.09
INTQ\  (via drill 0.6)
  Top 0.305: v98.1,50.32 v98.1,44.6
  Bottom 0.305: IC10.12 113.66,40.48 112.71,41.43 99.37,41.43 98.1,42.7 v98.1,44.6 | v98.1,50.32 94.29,50.32 93.34,51.27 91.12,51.27 90.48,50.63 79.05,50.63 75.88,53.81 63.5,53.81 62.23,52.54 51.43,52.54 49.53,50.63 37.46,50.63 34.92,48.09 IC9.12
METER+
  Bottom 0.305: LCL2.1 137.79,66.51 139.43,64.87 139.43,63.07 138.74,62.38 130.17,62.38 128.58,60.8 126.68,60.8 123.19,57.3 123.19,54.45 124.45,53.17 124.45,50.95 125.41,50 R7.2
N$1
  Bottom 0.305: IC13.7 113.66,27.14 112.39,28.41 C22.2
N$2
  Bottom 0.305: IC10.10 108.58,35.39 106.04,32.85 R26.1
N$3
  Bottom 0.305: Q3.E 100.96,10.63 | 100.96,10.63 Q4.E IC13.9 | 100.96,10.63 IC12.7 100.96,19.52 99.69,20.79 97.15,20.79 92.7,25.23 90.48,25.23 89.53,24.28 R35.1
N$4
  Top 0.305: IC12.3 98.42,23.33 95.88,20.79 IC12.5
  Bottom 0.305: R42.1 IC12.5 95.88,19.52 R36.2
N$5
  Bottom 0.61: R28.2 139.06,21.42 C24.1 131.44,16.98 IC13.16 128.9,15.71 D8.C
N$6
  Bottom 0.305: J4.1 146.27,55.49 142.87,58.89 LCL3.2
N$7
  Bottom 0.305: IC13.6 C22.1
N$8
  Bottom 0.305: IC6.5 60.32,70.64 61.27,71.59 66.99,71.59 68.26,70.32 68.26,69.37 IC6.2
N$9  (via drill 0.6)
  Top 0.305: v126.36,41.74 121.6,41.74 v119.69,43.65 | v100.01,44.6 100.01,50.95 99.05,52.22 v99.05,53.49
  Bottom 0.305: IC6.1 70.16,69.05 70.16,67.78 68.57,66.19 60.32,66.19 57.78,63.65 IC6.9 57.78,59.52 59.05,58.25 74.61,58.25 80.32,52.54 89.53,52.54 90.16,53.17 98.74,53.17 v99.05,53.49 | R23.1 128.58,30.95 126.68,32.85 126.68,41.43 v126.36,41.74 | v119.69,43.65 100.96,43.65 v100.01,44.6
N$10
  Bottom 0.305: R23.2 121.28,30.95 123.82,28.41 IC13.3
N$11
  Bottom 0.305: R46.2 117.47,10.63 116.2,11.9 IC13.11
N$12  (via drill 0.6)
  Top 0.305: v114.3,50.95 127.95,50.95 128.9,51.91 131.12,52.54 PC1.4
  Bottom 0.305: R10.1 135.25,46.19 133.98,47.46 133.98,51.27 132.71,52.54 PC1.4 | IC9.5 29.84,56.35 32.38,58.89 43.18,58.89 43.81,58.25 47.62,58.25 50.8,55.08 72.38,55.08 73.02,55.71 74.92,55.71 79.37,51.27 90.16,51.27 90.8,51.91 93.97,51.91 94.61,51.27 114.3,51.27 v114.3,50.95
N$13  (via drill 0.6)
  Top 0.305: v71.75,56.03 73.66,56.67 76.83,59.84 80,59.84 81.27,61.11 81.27,61.43 | IC7.6 81.59,63.97 81.27,63.65 81.27,61.43 | IC7.3 88.89,62.06 88.26,61.43 83.81,61.43 | 81.27,61.43 83.81,61.43 | 83.81,61.43 IC7.5
  Bottom 0.305: IC5.3 40,67.14 43.81,63.34 43.81,59.84 44.45,59.21 47.62,59.21 51.11,55.71 71.43,55.71 v71.75,56.03
N$14
  Bottom 0.305: R46.1 109.85,6.82 107.31,4.28 91.75,4.28 90.48,5.55 90.48,6.82 86.99,10.31 83.18,10.31 80.32,7.46 80.32,5.87 79.69,5.23 41.59,5.23 40.95,5.87 39.05,5.87 37.46,4.28 15.24,4.28 14.28,5.23 14.28,14.76 6.98,22.06 VR5.P_WIPE | VR5.P_WIPE VR5.P_WIPE1 | VR5.P_WIPE VR5.P_CCW
N$15
  Bottom 0.406: LCL2.2 142.87,75.4 146.48,79.01 J2.4
N$16  (via drill 0.6)
  Top 0.305: IC7.9 81.27,57.94 82.86,59.52 v84.77,59.52
  Bottom 0.305: IC7.8 IC7.9 | v84.77,59.52 86.35,61.11 IC7.4
N$17
  Bottom 0.305: R34.2 89.53,25.87 93.34,25.87 97.15,22.06 100.96,22.06 103.5,24.6 IC12.1 104.77,25.87 107.31,28.41 C20.1 108.58,32.22 109.85,33.49 113.02,33.49 114.3,34.76 114.3,35.39 113.66,36.03 112.39,36.03 111.12,37.3 IC10.11
N$18
  Bottom 0.305: IC6.11 62.86,59.21 63.18,58.89 81.27,58.89 IC7.10
N$19
  Top 0.305: C20.2 102.23,30.95 100.96,29.68 | 100.96,29.68 IC12.2 | R26.2 100.96,29.68
  Bottom 0.305: R26.2 95.24,29.04 88.89,29.04 85.08,25.23 85.08,19.52 72.07,6.5 42.54,6.5 41.91,7.14 37.78,7.14 36.51,5.87 16.82,5.87 16.19,6.5 16.19,17.93 7.3,26.82 7.3,37.94 6.66,38.57 VR4.P_CW
N$20
  Bottom 0.61: C25.2 138.11,10.63 123.82,10.63 | D9.C 123.82,10.63 | 123.82,10.63 D8.A 122.55,13.17 123.82,14.44 IC13.14
N$21
  Bottom 1.778: B1.+ 48.89,83.66 48.26,83.02 F1.1 40.95,83.02
N$22
  Bottom 0.305: R29.2 120.01,28.41 121.28,27.14 IC13.4
N$23  (via drill 0.6)
  Top 0.305: v75.24,64.92 66.99,64.92 65.08,66.83 65.08,68.73 IC6.3 | v125.09,40.16 124.45,40.79 119.06,40.79 v118.1,41.74 | v99.05,46.19 99.05,50.95 97.78,52.54 97.78,54.13 v99.69,55.08 | IC7.1 v93.97,58.57
  Bottom 0.305: IC7.1 IC7.2 91.44,65.56 90.16,66.83 78.1,66.83 76.19,64.92 v75.24,64.92 | R29.1 128.9,28.73 125.09,32.54 v125.09,40.16 | v118.1,41.74 118.1,42.06 117.47,42.7 100.32,42.7 99.05,43.97 v99.05,46.19 | v99.69,55.08 97.78,55.08 94.61,58.57 v93.97,58.57
N$24
  Bottom 0.305: R45.2 R41.1 | R45.2 R48.2 | IC14.9 R45.2
N$25
  Bottom 1.778: J1.1 31.74,84.29 33.65,86.19 33.65,87.47 35.55,89.37 B1.AC1
N$26
  Bottom 0.305: R5.2 133.98,55.71 135.25,54.45 135.25,48.73 136.52,47.46 PC1.1
N$27
  Top 0.305: R14.2 65.4,32.22 R22.1
  Bottom 0.305: R14.2 IC11.6
N$28
  Bottom 0.305: IC11.1 IC11.2 R14.1 R13.2
N$29
  Bottom 0.61: R39.2 140.01,16.98 C25.1
N$30
  Bottom 0.61: LCL5.2 142.87,37.3 146.68,41.11 J4.5 146.68,44.92
N$31  (via drill 0.6)
  Top 0.305: v114.61,58.57 108.58,58.57 v107.94,57.94 | v80.64,74.77 80,75.08 38.41,75.08 C13.1
  Bottom 0.305: IC8.1 120.01,60.48 118.74,59.21 115.25,59.21 v114.61,58.57 | v107.94,57.94 103.82,57.94 102.86,57.3 98.74,57.3 96.2,60.16 96.2,66.51 94.61,68.1 89.53,68.1 89.21,68.41 89.21,72.86 87.31,74.77 v80.64,74.77 | 36.51,73.18 C13.1 29.52,72.86 28.25,71.59 28.25,68.41 27.3,67.46 26.35,67.46 22.22,71.59 22.22,78.89 18.09,83.02 7.62,83.02 5.8,81.21 arc45 5.71,80.98 VR1.P_CW VR1.P_WIPE VR1.P_WIPE1
N$32  (via drill 0.6)
  Top 0.305: v45.08,73.5 46.03,74.45 77.78,74.45 v78.73,73.5
  Bottom 0.305: IC8.13 117.47,54.45 116.2,53.17 107.63,53.17 107.31,53.49 IC8.9 107.31,56.03 106.36,56.98 103.82,56.98 103.18,56.67 98.42,56.67 95.56,59.84 95.56,66.19 94.29,67.46 88.89,67.46 88.58,67.78 88.58,71.91 86.99,73.5 v78.73,73.5 | IC5.1 v45.08,73.5
N$33  (via drill 0.6)
  Top 0.305: IC9.11 32.38,48.09 34.92,50.63 IC9.3 | v67.94,56.67 IC6.13 | v49.84,52.86 v53.65,56.67
  Bottom 0.305: IC8.8 103.5,52.22 94.93,52.22 94.61,52.54 90.48,52.54 89.85,51.91 79.69,51.91 74.61,56.98 69.21,56.98 v67.94,56.67 v53.65,56.67 | IC9.3 34.92,56.03 35.87,56.98 42.86,56.98 43.18,56.67 46.03,56.67 v49.84,52.86
N$34  (via drill 0.6)
  Top 0.305: v102.86,55.71 v103.82,50.32 | v112.71,50.32 112.71,52.22 114.93,54.45 IC8.12
  Bottom 0.305: IC6.12 65.4,60.16 66.03,59.52 82.23,59.52 83.5,58.25 85.72,58.25 87.31,59.84 94.61,59.84 98.1,55.71 98.74,55.71 99.05,56.03 101.28,56.03 101.59,55.71 v102.86,55.71 | v103.82,50.32 v112.71,50.32
N$35  (via drill 0.6)
  Top 0.305: IC8.4 112.39,63.65 110.8,65.24 101.28,65.24 100.64,64.92 v97.47,64.92
  Bottom 0.305: v97.47,64.92 97.47,66.19 94.93,68.73 90.48,68.73 90.16,69.05 90.16,73.81 88.26,75.72 80.96,75.72 78.42,78.26 40.64,78.26 38.41,76.03 38.41,73.18 36.51,71.27 33.97,71.27 32.38,69.69 32.38,69.37 32.06,69.05 IC5.6
N$36
  Top 0.305: IC8.6 107.31,60.8 107.94,60.16 109.85,60.16 | 109.85,60.16 114.3,60.16 114.93,60.8 IC8.3 | 109.85,60.16 IC8.5
N$37
  Bottom 0.305: R43.2 142.87,6.82 C26.1
N$38
  Bottom 0.305: R32.1 R33.1 R38.2 IC14.11
N$39
  Top 0.305: IC9.1 40,56.35 37.46,58.89 IC5.11
  Bottom 0.305: IC9.9 27.3,50 29.84,52.54 39.72,52.5 40,52.82 IC9.1
N$40  (via drill 0.6)
  Top 0.305: IC5.8 29.84,58.25 32.38,55.71 IC9.4 | v73.97,54.76 74.61,53.81 v82.23,53.81
  Bottom 0.305: v73.97,54.76 73.66,54.45 59.37,54.45 59.05,54.13 50.16,54.13 46.98,57.3 43.49,57.3 42.86,57.94 33.97,57.94 32.38,56.35 IC9.4 | v82.23,53.81 85.72,53.81 86.35,54.45 IC7.11
N$41
  Bottom 0.305: R25.2 R22.2 IC11.7
N$42
  Bottom 0.305: Q4.B Q3.B 97.47,9.36 96.2,10.63 96.2,12.22 | 96.2,12.22 98.42,14.44 IC12.6 | R34.1 R35.2 90.8,14.44 93.34,14.44 94.61,13.17 95.24,13.17 96.2,12.22
N$43
  Bottom 0.305: LED1.A 8.25,89.37 9.52,88.1 R4.2
N$44
  Bottom 0.305: IC5.13 42.54,62.7 40.64,64.61 26.03,64.61 20.31,70.32 20.31,74.77 R4.1
N$45  (via drill 0.6)
  Top 0.305: R44.2 R40.2 | IC11.3 70.48,42.38 69.21,41.11 69.21,36.66 v69.84,36.03 | v44.45,22.06 41.91,19.52 IC14.4 | IC14.7 v40,4.6
  Bottom 0.305: C26.2 133.98,3.01 88.89,3.01 87.31,4.6 87.31,8.41 86.04,9.68 83.81,9.68 81.27,7.14 81.27,5.55 80.32,4.6 v40,4.6 | R40.2 31.11,16.98 34.92,20.79 D7.A | D7.A D6.C | D7.A 36.19,22.06 38.73,19.52 IC14.4 41.27,19.52 42.54,18.25 42.54,12.54 41.91,11.9 IC14.7 | v69.84,36.03 63.5,36.03 60.96,33.49 60.96,31.58 60.32,30.95 57.78,30.95 57.15,30.31 53.97,30.31 52.07,28.73 45.72,28.73 44.45,27.46 v44.45,22.06
N$46
  Top 0.305: R13.1 64.13,34.76 60.96,37.94 Q1.2
N$47
  Bottom 0.305: R20.2 111.12,34.76 109.85,36.03 109.85,39.84 109.21,40.79 106.99,40.79 106.04,39.84 IC10.9 R19.2
N$48
  Bottom 0.305: IC13.2 126.36,28.41 122.55,32.22 R20.1
N$49
  Bottom 0.305: R19.1 95.88,32.85 93.34,30.31 88.89,30.31 84.45,25.87 84.45,20.15 71.75,7.46 43.49,7.46 42.86,8.09 37.46,8.09 35.87,6.5 18.41,6.5 17.46,7.46 17.46,19.2 8.57,28.09 8.57,38.89 7.93,44.6 7.93,49.05 6.98,50 VR3.P_WIPE | VR3.P_WIPE 6.03,50 | 2.85,50 VR3.P_WIPE1 VR3.P_WIPE
N$50
  Bottom 0.305: IC10.8 103.5,36.03 98.42,30.95 98.42,30 96.52,28.09 89.21,28.09 85.72,24.6 85.72,18.88 72.7,5.87 42.22,5.87 41.59,6.5 38.41,6.5 37.14,5.23 16.19,5.23 15.55,5.87 15.55,17.61 5.71,27.46 VR4.P_CCW VR4.P_WIPE VR4.P_WIPE1
N$51
  Bottom 0.305: R50.1 95.88,6.82 103.5,6.82 Q4.C
N$52
  Bottom 0.305: R50.2 84.45,4.6 82.86,3.01 12.7,3.01 10.79,4.92 10.79,11.9 9.52,13.17 LED3.A
N$53
  Bottom 0.305: R49.2 83.81,8.09 82.55,6.82 82.55,4.6 81.59,3.64 13.97,3.64 12.06,5.55 LED4.K
N$54
  Bottom 0.305: R49.1 Q3.C
N$55
  Bottom 0.305: R44.1 R47.2 | R44.1 IC14.6 | R44.1 29.2,14.44 27.93,13.17 20,13.17 18.73,14.44 18.73,21.42 10.47,29.68 10.47,50.63 4.44,56.67 4.44,60.8 5.08,61.43 VR2.P_CCW
N$56
  Bottom 0.305: IC14.5 R40.1 R37.1 35.55,19.52 31.74,15.71 20.95,15.71 19.68,16.98 19.68,21.74 11.43,30 11.43,50.95 5.71,56.67 5.71,57.62 7.3,59.21 7.3,63.97 | 7.3,63.97 7.3,65.88 6.66,66.51 VR2.P_CW | 7.3,63.97 VR2.P_WIPE VR2.P_WIPE1 2.85,63.97
N$57
  Top 0.305: R25.1 58.41,29.68 57.15,30.95 Q2.2
N$58
  Bottom 0.305: R9.1 61.59,41.11 Q1.3 58.41,41.11 57.78,41.74 46.98,41.74 D2.C
N$59
  Bottom 0.305: R12.1 Q2.3 50.16,36.03 49.21,37.3 D3.C
N$60
  Bottom 0.305: D2.A R16.2 D3.A
N$61
  Bottom 0.305: R16.1 C18.1 49.53,39.84 50.8,38.57 R11.1 53.02,39.84 55.88,39.84 56.51,39.2 56.51,37.94 58.41,36.66 60.32,36.66 62.23,38.57 74.92,38.57 76.19,37.3 IC11.10
N$62
  Bottom 1.778: J1.3 38.73,94.45 41.27,91.91 46.35,91.91 B1.AC2
N$63
  Bottom 0.305: D5.C 74.29,30.31 76.19,32.22 IC11.8 81.27,32.22 R17.1
N$64
  Bottom 0.305: D4.C D5.A
N$65
  Bottom 0.305: IC11.9 76.83,34.76 71.75,29.68 D4.A 69.84,27.14 R31.1
N$66
  Bottom 0.305: R15.1 85.08,38.57 R17.2 82.55,41.74 IC11.13 78.73,44.92 77.46,46.19 77.46,49.37 R6.1
N$67
  Bottom 0.305: ZD1.C IC11.14
N$68
  Bottom 0.305: R15.2 85.08,43.65 86.35,44.92 ZD1.A R8.2 93.34,48.73 116.2,48.73 R7.1
N$69
  Bottom 0.305: R3.2 20,90.96 18.41,89.37 LED2.A
N$70
  Bottom 0.305: IC5.2 42.54,69.69 41.27,70.95 39.37,70.95 38.73,70.32 38.73,66.83 38.1,66.19 26.03,66.19 21.27,70.95 21.27,77.62 17.46,81.43 8.25,81.43 7.62,80.8 7.62,76.17 arc-45 7.52,75.94 6.98,75.4 VR1.P_CCW
N$71
  Bottom 0.61: R27.1 135.25,25.87 132.71,25.87 131.44,24.6 131.44,22.06 130.17,20.79 120.01,20.79 118.74,19.52 IC13.12
N$72
  Bottom 0.305: R27.2 R18.1 132.71,33.49 131.44,34.76 C19.1
N$73
  Bottom 0.305: 125.41,91.91 R2.1
  Bottom 1.676: IC2.7 125.41,91.91 128.9,91.91 C1.1 | IC2.6 131.44,89.37 C5.1
  pour Bottom: 127.63,88.1 127.63,96.99 144.46,96.99 144.46,89.37 143.19,88.1
  pour Bottom: 115.56,92.23 128.58,92.23 128.58,89.05 115.56,89.05
N$74
  Bottom 1.778: F1.2 57.46,83.02 55.24,85.24 LCL1.1
N$75
  Bottom 0.305: IC14.10 46.35,16.98 45.4,16.03 45.4,11.9 | 45.4,10.63 45.4,11.9 | 45.4,10.63 46.67,9.36 ZD2.C R51.2 | 45.4,11.9 IC14.8 | C27.1 34.6,9.36 35.87,10.63 45.4,10.63
N$666  (via drill 0.6)
  Top 0.305: D14.C 100.96,40.16 101.59,40.79 v101.59,50.32 | v117.15,52.22 117.79,51.59 127.63,51.59 v129.22,53.49
  Bottom 0.305: R53.2 130.49,59.84 129.85,59.21 129.22,59.21 | 129.22,59.21 C28.1 | D14.C 100.01,38.89 R52.2 | v101.59,50.32 102.55,49.37 114.93,49.37 v117.15,52.22 | v129.22,53.49 129.22,59.21
OUT
  Bottom 1.676: 127.95,80.48 IC3.7 | 127.95,80.48 139.06,84.29 146.68,84.29 J2.2 | IC3.6 127.95,77.94 127.95,80.48
  pour Bottom: 127.63,87.15 143.82,87.15 145.73,89.37 147.95,89.37 147.95,83.02 145.41,83.02 131.44,74.13 127.63,74.13
  pour Bottom: 115.88,80.8 128.58,80.8 128.58,77.62 115.88,77.62
OUT\
  Top 0.305: R2.2 133.03,85.56 134.62,87.15 C5.2
  pour Top: 127.63,96.99 144.46,96.99 144.46,90.64 151.76,90.64 151.76,83.02 127.63,83.02
SYNC  (via drill 0.6)
  Top 0.305: J3.1 130.17,72.86 128.9,71.59 94.61,71.59 93.34,72.86 93.34,77.94 92.07,79.21 v66.67,79.21
  Bottom 0.305: v66.67,79.21 D1.A
  Bottom 1.778: LCL1.2 R1.2 D1.A
TRIAC
  Bottom 0.406: J3.6 J2.3
UNREG  (via drill 0.6)
  Top 0.305: v97.15,46.19 96.83,46.51 96.83,54.45 101.28,58.57 v102.23,58.57
  Top 1.676: IC4.IN v105.41,70.32 93.34,70.32 92.07,71.59 v92.07,75.4
  Bottom 0.305: R45.1 62.54,14.44 65.08,11.9 | 65.08,11.9 74.29,11.9 83.18,20.79 83.18,25.87 89.53,32.22 90.8,32.22 97.15,38.57 v97.15,46.19 | v102.23,58.57 102.23,60.8 102.86,61.43 102.86,66.51 105.41,69.05 v105.41,70.32 | R51.1 62.54,9.36 65.08,11.9
  Bottom 1.676: v92.07,75.4 88.26,78.58 88.26,89.37 | 88.26,89.37 IC1.IN | 88.26,89.37 77.46,91.91 C7.+
  Bottom 1.778: D1.C 70.48,91.91 77.46,91.91
VCC/2
  Top 0.305: IC11.5 74.29,34.76 76.19,34.76 78.1,42.38 IC11.12
  Bottom 0.305: R24.1 42.54,33.49 | 42.54,33.49 R21.2 | 42.54,33.49 43.18,33.49 43.81,32.85 43.81,31.9 44.76,30.95 C21.1 46.35,32.22 51.43,32.22 52.07,31.58 56.51,31.58 62.23,37.3 IC11.5
VOLT_F
  Bottom 0.305: LCL3.1 137.47,63.97 135.88,65.56 135.88,73.81 135.25,74.45 J3.3

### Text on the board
tPlace: LIMIT/ | POWER | FAULT | GATE DRIVE | :-) | DIMMER SW. | 15V AC IN | S J C | DEAD- | TIME | LIMIT | CURRENT | DRIVER | INTERRUPTER | PHASE | TARGET | LOOP | GAIN | *SSTC | PHASE LOCKED LOOP | TUNING | File name | MADE IN SCOTLAND BY STEVE CONNER 2004-2006 | TUNING AID | MAY CONTAIN TRACES OF NUT | LOW | HIGH | CURRENT SENSOR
